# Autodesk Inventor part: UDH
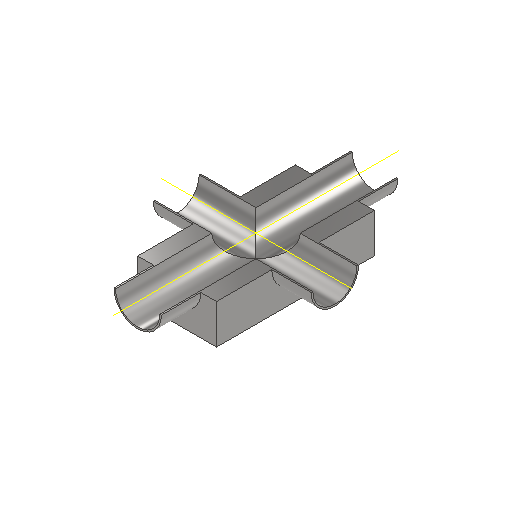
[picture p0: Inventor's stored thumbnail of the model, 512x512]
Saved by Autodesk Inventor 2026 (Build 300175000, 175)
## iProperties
Created: 2022-10
Part Number: UDH
Material: Steel, Mild
Document SubType Name: Modeling
Designer: Lars Bertram Pedersen
Density: 7.85 g/cm^3
Appearance: Semi-Polished
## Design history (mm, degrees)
sketch "Sketch1"
  geometry: L1 (0, 0)-(50, 0); L2 (50, 0)-(50, 25); L3 (50, 25)-(0, 25); L4 (0, 25)-(0, 0)
  constraints: 8 end point, 2 parallel, 1 horizontal, 1 perpendicular
  dimensions: "d0" = 50 distance of L3.end L2.end; "d1" = 25 distance of L2.end L1.end
extrude "Extrusion1" new body sketch "Sketch1" distance "d2" = 100; taper "d3" = 0 deg
workplane "Work Plane2"
sketch "Sketch4"
  geometry: L1 (0, 25)-(100, 25) reference; A1 r 15 centre (50, 25) between (35, 25) and (65, 25); 1 further point
  constraints: 2 point on circle, 2 point on line, 1 centre point, 1 midpoint
  dimensions: "d8" = 15 radius of A1
extrude "Extrusion2" join sketch "Sketch4" distance "d9" = 100; taper "d10" = 0 deg
workplane "Work Plane4"
sketch "Sketch7"
  geometry: L1 (100, -15)-(75, -15) reference; L2 (75, -15)-(75, -25) reference; L3 (75, -25)-(25, -25) reference; L4 (25, -25)-(25, -15) reference; L5 (25, -15)-(0, -15) reference; L6 (0, -15)-(0, 0) reference; L7 (0, 0)-(100, 0) reference; L8 (100, 0)-(100, -15) reference; A1 r 15 centre (50, 0) between (35, 0) and (65, 0)
  constraints: 2 point on circle, 2 point on line, 1 centre point, 1 midpoint
  dimensions: "d15" = 15 radius of A1
extrude "Extrusion4" join sketch "Sketch7" stored distance "d16" = 150; taper "d17" = 0 deg
sketch "Sketch8"
  geometry: L1 (36, 0)-(64, 0); A1 r 15 centre (50, 0) between (35, 0) and (65, 0) reference; A2 r 14 centre (50, 0) between (36, 0) and (64, 0); 1 further point
  constraints: 2 end point, 2 point on circle, 1 centre point, 1 horizontal
  dimensions: "d18" = 1 radial gap between concentric circles of A1 A2
extrude "Extrusion5" cut sketch "Sketch8" extent not by distance; stored distance "d19" = 0; taper "d20" = 0 deg
sketch "Sketch9"
  geometry: L1 (-64, 25)-(-36, 25); A1 r 15 centre (-50, 25) between (-65, 25) and (-35, 25) reference; A2 r 14 centre (-50, 25) between (-64, 25) and (-36, 25); 1 further point
  constraints: 2 end point, 2 point on circle, 1 centre point, 1 horizontal
  dimensions: "d21" = 1 radial gap between concentric circles of A1 A2
extrude "Extrusion6" cut sketch "Sketch9" extent not by distance; stored distance "d22" = 0; taper "d23" = 0 deg
workaxis "Work Axis1"
workaxis "Work Axis2"
sketch "Sketch6"
  geometry: L1 (75, 0)-(25, 0) reference; A1 r 15 centre (50, 0) between (35, 0) and (65, 0); 1 further point
  constraints: 2 point on circle, 2 point on line, 1 centre point, 1 midpoint
  dimensions: "d12" = 15 radius of A1
extrude "Extrusion3" join sketch "Sketch6" stored distance "d13" = 150; taper "d14" = 0 deg
body "Solid1"
node "Project Cut Edges1"
other parameters: "d6" = 25
